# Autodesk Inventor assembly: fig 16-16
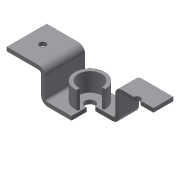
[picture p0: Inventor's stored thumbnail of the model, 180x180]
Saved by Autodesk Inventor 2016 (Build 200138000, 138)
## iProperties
Created: 2005-03
Part Number: fig 16-16
Document SubType Name: Weldment
Designer: CADCIM
Manufacturer: Standard
Standards Organization: Custom
Author: CADCIM
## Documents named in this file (3)
- D:\KAVITA\Autodesk Inventor_ 2016 Project_Kavita\Inventor_Part Files\Inventor_2016_Part\c16_Inv_2016\c16_inv_2016_prt\fig 16-16\fig 16-16.iam
- D:\KAVITA\Autodesk Inventor_ 2016 Project_Kavita\Inventor_Part Files\Inventor_2016_Part\c16_Inv_2016\c16_inv_2016_prt\fig 16-16\Bracket.ipt
- D:\KAVITA\Autodesk Inventor_ 2016 Project_Kavita\Inventor_Part Files\Inventor_2016_Part\c16_Inv_2016\c16_inv_2016_prt\fig 16-16\cylinder.ipt
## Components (2 placed, 2 different names)
1. Bracket:1 — Insert:1
2. cylinder:1 — Insert:1
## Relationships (1: Insert 1)
- Insert:1: Bracket:1 ↔ cylinder:1
